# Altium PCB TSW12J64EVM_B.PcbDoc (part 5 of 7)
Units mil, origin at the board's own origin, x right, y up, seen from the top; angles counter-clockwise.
Board outline 8833 x 2680 mil, 10 copper layers (Top Layer L1, Gnd-Plane - L2, Signals - L3, Gnd-Plane - L4, Pwr Plane - L5, Signals - L6, Gnd-Plane - L7, Signals - L8, Gnd-Plane - L9, Bottom Layer - L10), stack 57.8 mil thick; 950 components, 533 nets, 2888 pads, 1732 vias.
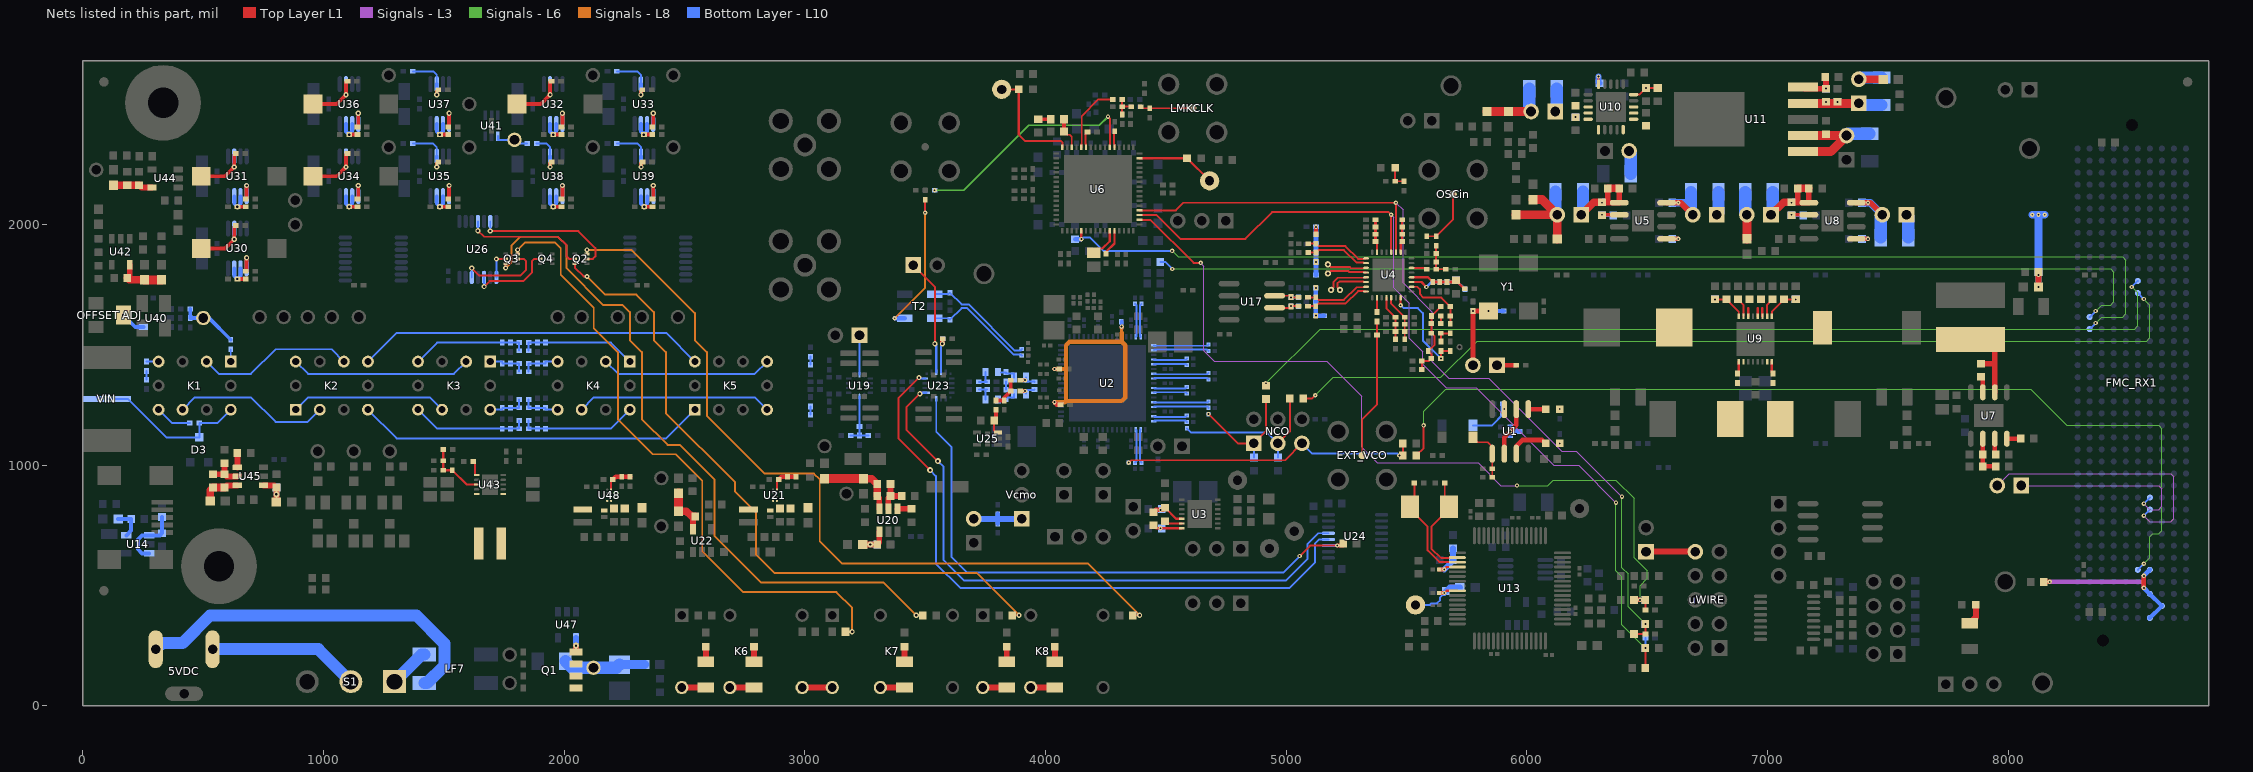
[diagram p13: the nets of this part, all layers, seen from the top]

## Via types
v1: diameter 18, hole 8, Top Layer L1 to Bottom Layer - L10, tented both sides, 1096 vias
v2: diameter 21.46, hole 10, Top Layer L1 to Bottom Layer - L10, tented both sides, 266 vias
v3: diameter 25, hole 10, Top Layer L1 to Bottom Layer - L10, tented both sides, 154 vias
v4: diameter 19.68, hole 7.87, Top Layer L1 to Bottom Layer - L10, 103 vias
v5: diameter 18, hole 8, Top Layer L1 to Bottom Layer - L10, tented bottom, 42 vias
v6: diameter 18, hole 8, Top Layer L1 to Bottom Layer - L10, tented top, 24 vias
v7: diameter 18, hole 8.01, Top Layer L1 to Bottom Layer - L10, tented both sides, 16 vias
v8: diameter 18, hole 8.01, Top Layer L1 to Bottom Layer - L10, tented bottom, 16 vias
v9: diameter 25.98, hole 12.99, Top Layer L1 to Bottom Layer - L10, tented top, 8 vias
v10: diameter 19.68, hole 7.87, Top Layer L1 to Bottom Layer - L10, tented top, 5 vias
v11: diameter 126, hole 106, Top Layer L1 to Bottom Layer - L10, tented top, 2 vias

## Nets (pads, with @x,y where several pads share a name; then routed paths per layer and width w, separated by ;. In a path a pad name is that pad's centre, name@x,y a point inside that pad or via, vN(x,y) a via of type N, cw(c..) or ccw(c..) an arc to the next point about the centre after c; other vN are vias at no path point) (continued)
LMH_SCSB: R187.1 U23.15 U24.11 | length 2428.3
  Top Layer L1 w8: v1(5056.02,622.21) 5099.42,665.61 v1(5212.13,665.61)
  Top Layer L1 w18: v1(5212.13,665.61) 5236.88,665.61 R187.1@5236.88,673.35
  Bottom Layer - L10 w8: U23.15@3546.04,1275.04 3546.04,1138.33 3609,1075.37 3609,619 3675,553 4986.8,553 v1(5056.02,622.21)
  Bottom Layer - L10 w13: U24.11@5175.57,665.61 v1(5212.13,665.61)
LMH_SDI: U23.1 U24.13 | length 2558.2
  Top Layer L1 w8: v2(3478.22,1296.66) 3422,1240.44 3422,1147.63 v3(3553,1016.63)
  Bottom Layer - L10 w8: v3(3553,1016.63) 3577,992.63 3577,605 3661,521 5000.06,521 5088.01,608.96 5088.01,671.18 5133.63,716.8 U24.13@5175.57,716.8
  Bottom Layer - L10 w9.84: v2(3478.22,1296.66) 3482.19,1300.63 U23.1@3504.7,1300.63
LMH_SDO: U23.4 U24.12 | length 2702.9
  Top Layer L1 w8: v2(3474.28,1363.65) 3390,1279.37 3390,1109.63 v3(3521,978.63)
  Bottom Layer - L10 w8: v3(3521,978.63) 3545,954.63 3545,591 3647,489 5013.31,489 5120.01,595.7 5120.01,674.9 5136.32,691.2 U24.12@5175.57,691.2
  Bottom Layer - L10 w9.84: v2(3474.28,1363.65) 3478.25,1359.68 U23.4@3500.76,1359.68
LMK04828_CSB: R68.1 R69.1 R98.1 R104.2 U6.18 | length 3453.2
  Top Layer L1 w8: U6.18@4390.79,2019.05 4435.95,2019.05 4615,1840 v1(4645,1840) ; R104.2@6492.44,398 R98.1@6492.44,440
  Top Layer L1 w18: R68.1@6445,440 R98.1@6492.44,440
  Signals - L3 w4: v1(4645,1840) 4658,1827 4658,1474 4701,1431 5169,1431 5313,1287 5313,1075 5378,1010 5797,1010 5892,915 v1(5959,915)
  Signals - L6 w4: v1(5959,915) 6087,915 6110,938 6370,938 6445,863 6445,616 6501,560 6501,529 6470.56,498.56 v1(6470.56,440)
  Bottom Layer - L10 w8: v1(6470.56,440) R69.1@6492.44,440
LMK04828_RESET: FMC_RX1.J16 R122.2 U6.5 | length 4841.4
  Top Layer L1 w9: v1(4148.66,1938.69) U6.5@4148.66,1973.77
  Signals - L6 w4: v1(4526,1890) 4551,1865 8475,1865 8488,1852 8488,1628 8475,1615 8388,1615 v5(8363,1590)
  Bottom Layer - L10 w8: v1(4148.66,1938.69) 4154.98,1945 4185,1945 4240,1890 v1(4526,1890) ; FMC_RX1.J16@8338,1565 v5(8363,1590)
  Bottom Layer - L10 w18: R122.2@4122.93,1938.69 v1(4148.66,1938.69)
LMK04828_SYNC: FMC_RX1.J15 R142.1 | length 4227.5
  Signals - L6 w4: v1(4526.55,1815) 8425,1815 8438,1802 8438,1678 8425,1665 8388,1665 v5(8363,1640)
  Bottom Layer - L10 w8: R142.1@4477.56,1843 4498.55,1843 v1(4526.55,1815) ; FMC_RX1.J15@8338,1615 v5(8363,1640)
LMK_TRF_CLK: R102.1 R115.1 R121.1 R129.2 U4.4 U6.19 | length 3794
  Top Layer L1 w8: U6.19@4390.79,2038.73 4461.27,2038.73 4560,1940 4830,1940 4941,2051 5425.08,2051 v1(5436.08,2040) U4.4@5436.08,1884.49 ; R102.1@6485.63,240 v1(6492.44,240) R115.1@6492.44,157.56
  Signals - L3 w4: v1(5436.08,2040) 5445.92,2030.16 5445.92,1737.08 5511,1672 5511,1527 5568,1470 5568,1419 5665,1322 5789,1322 6112.5,998.5 6215.5,998.5 v1(6370,844)
  Signals - L6 w4: v1(6370,844) 6370,560.44 6395,535.44 6395,337.44 v1(6492.44,240)
  Bottom Layer - L10 w8: v1(6492.44,240) R129.2@6492.44,282
LMK_TRF_DATA: R101.1 R114.1 R120.1 R128.2 U4.3 U6.20 | length 3686
  Top Layer L1 w8: U6.20@4390.79,2058.42 4541.42,2058.42 4573,2090 v1(5455.76,2090) U4.3@5455.76,1884.49 ; R114.1@6445,298 R128.2@6492.44,298 v1(6492.44,340)
  Signals - L3 w4: v1(5455.76,2090) 5485.29,2060.47 5485.29,1756.54 5607,1634.83 5607,1429 5675,1361 5841,1361 6144,1058 6206,1058 v1(6395,869)
  Signals - L6 w4: v1(6395,869) 6395,573 6420,548 6420,412.44 v1(6492.44,340)
LO1_N: C83.1 R34.2 U4.10 | length 266.8
  Top Layer L1 w8: C83.1@5091.73,1883.18 R34.2@5124.05,1883.18 5134.36,1893.5 5239.68,1893.5 5292.12,1841.05 5321.86,1841.05 5323.7,1839.21 U4.10@5331.75,1839.21
LO1_P: C75.1 R27.2 U4.9 | length 266.8
  Top Layer L1 w8: C75.1@5091.73,1919.81 R27.2@5124.05,1919.81 5134.36,1909.5 5246.3,1909.5 5298.75,1857.05 5321.86,1857.05 5323.7,1858.9 U4.9@5331.75,1858.9
LO2_N: LO2_N.1 U4.11 | length 166.2
  Top Layer L1 w8: LO2_N.1@5173.05,1833.99 5184.04,1823 5263.8,1823 5269.12,1817.68 5321.86,1817.68 5323.7,1819.53 U4.11@5331.75,1819.53
LO2_P: LO2_P.1 U4.12 | length 166.2
  Top Layer L1 w8: LO2_P.1@5173.05,1796.01 5184.04,1807 5257.18,1807 5262.49,1801.68 5321.86,1801.68 5323.7,1799.84 U4.12@5331.75,1799.84
LO3_N: LO3_N.1 U4.14 | length 153.6
  Top Layer L1 w8: LO3_N.1@5223.32,1728 5213,1738.31 5213,1754.63 5220.69,1762.31 5321.86,1762.31 5323.7,1760.47 U4.14@5331.75,1760.47
LO3_P: LO3_P.1 U4.13 | length 180.1
  Top Layer L1 w8: LO3_P.1@5186.69,1728 5197,1738.32 5197,1761.26 5214.06,1778.32 5321.86,1778.32 5323.7,1780.16 U4.13@5331.75,1780.16
LO4_N: C84.1 R35.2 U4.15 | length 267.8
  Top Layer L1 w8: C84.1@5090.73,1696.81 R35.2@5123.05,1696.81 5133.36,1686.5 5239.68,1686.5 5292.12,1738.95 5321.86,1738.95 5323.7,1740.79 U4.15@5331.75,1740.79
LO4_P: C76.1 R28.2 U4.16 | length 267.8
  Top Layer L1 w8: C76.1@5090.73,1660.18 R28.2@5123.05,1660.18 5133.36,1670.5 5246.3,1670.5 5298.75,1722.94 5321.86,1722.94 5323.7,1721.1 U4.16@5331.75,1721.1
NCO-0: NCO.1 R6.2 R7.1 R136.1 | length 502.4
  Top Layer L1 w8: v1(4677.2,1211.93) 4799.13,1090 NCO.1@4865.5,1090 4915.5,1140 R136.1@4915.5,1274.44
  Bottom Layer - L10 w8: R6.2@4865.5,1031.56 NCO.1@4865.5,1090
NCO-1: NCO.3 R5.2 R8.1 R137.1 | length 669.5
  Top Layer L1 w8: NCO.3@4965.5,1090 5015.5,1140 R137.1@5015.5,1276
  Bottom Layer - L10 w8: R8.1@4587.2,1152.88 4605.27,1134.81 4920.69,1134.81 NCO.3@4965.5,1090 R5.2@4965.5,1031.56
NCO-2: NCO.5 R4.2 R9.1 R138.1 | length 1227.9
  Top Layer L1 w8: v1(4345.86,1010.18) 4355.67,1020 4995.5,1020 NCO.5@5065.5,1090 ; R138.1@5484.94,1040 R4.2@5484.94,1090
  Bottom Layer - L10 w8: NCO.5@5065.5,1090 5106.5,1049 5461,1049 v1(5470,1040)
NCO_0: FMC_RX1.E12 R136.2 | length 3928.8
  Signals - L6 w4: v1(4915.5,1340) 5140.5,1565 8525,1565 8538,1578 8538,1715 v5(8513,1740)
  Bottom Layer - L10 w8: v5(8513,1740) FMC_RX1.E12@8538,1765
NCO_1: FMC_RX1.E13 R137.2 | length 3829.5
  Top Layer L1 w8: R137.2@5070.62,1276 5106.62,1276 v1(5120.62,1290)
  Signals - L6 w4: v1(5120.62,1290) 5195.62,1365 5643,1365 5793,1515 8575,1515 8588,1528 8588,1665 v5(8563,1690)
  Bottom Layer - L10 w8: FMC_RX1.E13@8538,1715 v5(8563,1690)
NCO_2: FMC_RX1.E36 R138.2 | length 4010.9
  Top Layer L1 w8: R138.2@5540.06,1040 5571,1070.94 v1(5571,1165)
  Signals - L6 w4: v1(5571,1165) 5571,1223 5663,1315 8093,1315 8243,1165 8625,1165 8638,1152 8638,728 8625,715 8601,715 8588,702 8588,615 v5(8563,590)
  Bottom Layer - L10 w8: FMC_RX1.E36@8538,565 v5(8563,590)
"Net1:1 Atten_1": "1:1 Atten.1" R253.2 | length 63.2
  Top Layer L1 w24: R253.2@3414,182.3 3414,245.47
Net1:1_2: 1:1.2 R235.1 U32.2 | length 256.4
  Top Layer L1 w15.75: 1:1.2@1804.52,2500 1903.36,2500 v2(1941.84,2538.48) 1941.84,2589.09 R235.1@1947.74,2595
  Bottom Layer - L10 w15.75: v2(1941.84,2538.48) U32.2@1941.84,2582.68
Net1V2ADC_INT_2: 1V2ADC_INT.2 C172.1 R83.2 U10.5 U10.6 U10.7 U10.8 | length 97.4
  Bottom Layer - L10 w51: 1V2ADC_INT.2@6424.26,2305 6431.35,2297.91 R83.2@6431.35,2210.56
Net1V2ADC_LDO_1: 1V2ADC_LDO.1 C185.1 C195.1 R84.1 R85.2 U10.1 U10.18 U10.19 U10.20 | length 97.4
  Bottom Layer - L10 w51: 1V2ADC_LDO.1@6117.27,2469 6124.35,2476.09 R84.1@6124.35,2563.44
  other v1: 6202.68,2445.56
Net1V2ADC_LDO_2: 1V2ADC_LDO.2 L15.1 L16.1 R84.2 | length 279.6
  Top Layer L1 w37: L15.1@5835,2469 L16.1@5923,2469 1V2ADC_LDO.2@6017.27,2469
  Bottom Layer - L10 w51: R84.2@6010.18,2563.44 6010.18,2476.09 1V2ADC_LDO.2@6017.27,2469
Net1V9ADC_1: 1V9ADC.1 C192.1 C198.1 C204.1 R92.1 R93.2 U11.4 | length 377.2
  Top Layer L1 w37: U11.4@7147.22,2502.93 1V9ADC.1@7379,2502.93
  Bottom Layer - L10 w24: v1(7243,2508.83) v1(7291,2508.83)
  Bottom Layer - L10 w51: 1V9ADC.1@7379,2502.93 7386.09,2495.84 R92.1@7473.44,2495.84
Net1V9ADC_2: 1V9ADC.2 L18.1 R92.2 | length 197.9
  Top Layer L1 w31.5: 1V9ADC.2@7379,2602.93 L18.1@7479.5,2602.93
  Bottom Layer - L10 w51: 1V9ADC.2@7379,2602.93 7386.09,2610.02 R92.2@7473.44,2610.02
Net1V9INT_2: 1V9INT.2 C196.1 R95.2 U11.1 U11.2 | length 487
  Top Layer L1 w37: U11.1@7147.22,2302.14 7262.07,2302.14 1V9INT.2@7328,2369.07 U11.2@7147.22,2369.07
  Bottom Layer - L10 w51: 1V9INT.2@7328,2369.07 7335.09,2376.16 R95.2@7422.44,2376.16
"Net2:1 Atten_1": "2:1 Atten.1" R252.1 | length 63.2
  Top Layer L1 w24: R252.1@2789,182.3 2789,245.47
Net2:1_2: 2:1.2 R237.1 U34.2 | length 256.4
  Top Layer L1 w15.75: 2:1.2@956.52,2200 1055.36,2200 v2(1093.84,2238.48) 1093.84,2289.09 R237.1@1099.74,2295
  Bottom Layer - L10 w15.75: v2(1093.84,2238.48) U34.2@1093.84,2282.68
Net3P3USB_1: 3P3USB.1 C139.1 C140.1 L24.2 U13.9 | length 301.4
  Top Layer L1 w10: v1(5656.5,468.31) 5666.34,478.16 U13.9@5710.97,478.16
  Top Layer L1 w16.5: C140.1@5635.44,468.32 v1(5656.5,468.31)
  Bottom Layer - L10 w8: 3P3USB.1@5537,419 5597,419 5603,425 5626,425 5639,438 5639,450.81 v1(5656.5,468.31)
  Bottom Layer - L10 w24: v1(5656.5,468.31) 5679.18,491 L24.2@5721.5,491
"Net5:1 Atten_1": "5:1 Atten.1" R251.2 | length 63.2
  Top Layer L1 w24: R251.2@2589,182.3 2589,245.47
Net5:1_2: 5:1.2 R238.1 U36.2 | length 256.4
  Top Layer L1 w15.75: 5:1.2@956.52,2500 1055.36,2500 v2(1093.84,2538.48) 1093.84,2589.09 R238.1@1099.74,2595
  Bottom Layer - L10 w15.75: v2(1093.84,2538.48) U36.2@1093.84,2582.68
Net5VDC_1: 5VDC.1 S1.2 | length 630.5
  Bottom Layer - L10 w50: 5VDC.1@539.37,235 979.2,235 S1.2@1114,100.2
Net5VDC_2: 5VDC.2 LF7.1 | length 1511.5
  Bottom Layer - L10 w50: 5VDC.2@303.15,235 329.15,261 415,261 529.51,375.51 1385.79,375.51 1503,258.31 1503,166.89 1430.6,94.49 LF7.1@1419.55,94.49
Net12V_1: 12V.1 R94.1 | length 88.2
  Top Layer L1 w25: R94.1@7840,342.15 7865,367.15 12V.1@7865,420
"Net5401 PD_1": "5401 PD.1" U19.9 | length 163.6
  Bottom Layer - L10 w8: U19.9@3227.22,1375.43 3227.22,1539
"Net6401 PD_1": "6401 PD.1" U23.6 | length 485.5
  Top Layer L1 w8: 3450.06,1831 3540.23,1740.83 v2(3540.23,1504.43)
  Bottom Layer - L10 w9.84: v2(3540.23,1504.43) 3546.04,1498.61 U23.6@3546.04,1385.28
Net+5_1: +5.1 C193.1 F1.1 L17.1 Q1.1 Q1.2 Q1.3 | length 346.3
  Bottom Layer - L10 w37: C193.1@2230,171.39 L17.1@2334.5,171.39
  Bottom Layer - L10 w50: F1.1@2005.09,185.3 2032.39,158 +5.1@2122,158 2216.61,158 C193.1@2230,171.39
"NetAC COUPLED_1": "AC COUPLED.1" R254.2 | length 63.2
  Top Layer L1 w24: R254.2@3839,182.3 3839,245.47
NetAC_2: AC.2 R236.1 U31.2 | length 256.4
  Top Layer L1 w15.75: AC.2@492.52,2200 591.36,2200 v2(629.84,2238.48) 629.84,2289.09 R236.1@635.74,2295
  Bottom Layer - L10 w15.75: v2(629.84,2238.48) U31.2@629.84,2282.68
NetC1_2: C1.2 R184.2 R185.1 R190.2 | length 129.3
  Top Layer L1 w16: R190.2@3794.43,1268.69 C1.2@3828.43,1268.69 3828.43,1280.56 R184.2@3855.42,1307.55 R185.1@3855.42,1352.76
NetC2_1: C2.1 D2.1 R3.2 U1.3 | length 187.3
  Bottom Layer - L10 w8: D2.1@5775.95,1165 5855.02,1165 C2.1@5900.69,1210.67
  Bottom Layer - L10 w19.5: C2.1@5900.69,1210.67 R3.2@5900.69,1254.36
  other v1: 5906,1232.52
NetC7_2: C7.2 U2.33 | length 139.9
  Bottom Layer - L10 w8: U2.33@4395.18,1532.91 4393.34,1534.76 4393.34,1664.32 C7.2@4398.84,1669.81
NetC8_1: C8.1 D4.1 R11.2 U1.5 | length 222.2
  Top Layer L1 w8: D4.1@5775.95,1115 5795.95,1095 5837,1095 5856,1076 U1.5@5856,1047.48 C8.1@5856,985 R11.2@5856,950
NetC9_2: C9.2 U2.32 | length 139.9
  Bottom Layer - L10 w8: C9.2@4371.84,1669.81 4377.34,1664.31 4377.34,1534.76 U2.32@4375.5,1532.91
NetC10_2: C10.2 U2.36 | length 229.9
  Bottom Layer - L10 w8: U2.36@4450.3,1477.8 4452.14,1479.64 4671.7,1479.64 C10.2@4677.2,1474.14
NetC11_1: C11.1 R1.1 R12.2 U1.2 U1.6 | length 281.1
  Top Layer L1 w19.5: U1.6@5906,1047.48 5906,1115 v1(5931,1140) 5956,1165 U1.2@5956,1232.52
  Bottom Layer - L10 w19.5: R12.2@5931,1122 C11.1@5931,1158 ; v1(5931,1140) R1.1@5970.31,1140
NetC12_2: C12.2 U2.35 | length 229.9
  Bottom Layer - L10 w8: U2.35@4450.3,1497.48 4452.14,1495.64 4671.7,1495.64 C12.2@4677.2,1501.14
NetC13_2: C13.2 U2.39 | length 139.9
  Bottom Layer - L10 w8: U2.39@4450.3,1418.74 4452.14,1420.58 4581.7,1420.58 C13.2@4587.2,1415.08
NetC14_2: C14.2 U2.38 | length 139.9
  Bottom Layer - L10 w8: U2.38@4450.3,1438.43 4452.14,1436.58 4581.7,1436.58 C14.2@4587.2,1442.08
NetC15_2: C15.2 U2.42 | length 229.9
  Bottom Layer - L10 w8: U2.42@4450.3,1359.68 4452.14,1361.53 4671.7,1361.53 C15.2@4677.2,1356.03
NetC16_2: C16.2 C18.2 C19.2 U2.5 U2.12 U2.29 | length 1287.4
  Top Layer L1 w18: v1(4037.26,1261.26) 4047.31,1251.21 C18.2@4062.57,1251.2 ; v1(4037.26,1399.05) C19.2@4057.52,1399.05
  Signals - L8 w13: 4316.44,1549.33 v1@4316.44,1570.92
  Signals - L8 w18: v1(4037.26,1261.26) 4080.22,1261.26 4085.14,1266.18 ; v1(4037.26,1399.05) 4085.14,1399.05 ; 4084.79,1497.48 4099.56,1512.24 4316.79,1512.24 ; 4085.14,1497.83 4085.14,1266.18 ; 4316.44,1549.33 4316.44,1512.59 4331.2,1497.83 4331.2,1280.6 4316.79,1266.18 4085.14,1266.18 ; v1@4316.44,1570.92 v1(4316.44,1575.13)
  Bottom Layer - L10 w9: v1(4037.26,1261.26) U2.5@4064.47,1261.26 ; v1(4037.26,1399.05) U2.12@4064.47,1399.06 ; U2.29@4316.44,1532.91 v1(4316.44,1575.13)
  Bottom Layer - L10 w16: v1(4316.44,1575.13) C16.2@4316.44,1595.94
NetC17_2: C17.2 U2.41 | length 229.9
  Bottom Layer - L10 w8: U2.41@4450.3,1379.37 4452.14,1377.53 4671.7,1377.53 C17.2@4677.2,1383.03
NetC20_2: C20.2 U2.45 | length 139.9
  Bottom Layer - L10 w8: U2.45@4450.3,1300.63 4452.14,1302.47 4581.7,1302.47 C20.2@4587.2,1296.97
NetC21_2: C21.2 U2.44 | length 139.9
  Bottom Layer - L10 w8: U2.44@4450.3,1320.31 4452.14,1318.47 4581.7,1318.47 C21.2@4587.2,1323.97
NetC22_2: C22.2 R7.2 U2.48 | length 229.9
  Bottom Layer - L10 w8: U2.48@4450.3,1241.57 4452.14,1243.42 4671.7,1243.42 R7.2@4677.2,1237.92
NetC23_2: C23.2 U2.47 | length 229.9
  Bottom Layer - L10 w8: U2.47@4450.3,1261.26 4452.14,1259.42 4671.7,1259.42 C23.2@4677.2,1264.92
NetC26_2: C26.2 R8.2 U2.51 | length 139.9
  Bottom Layer - L10 w8: U2.51@4450.3,1182.52 4452.14,1184.36 4581.7,1184.36 R8.2@4587.2,1178.86
NetC28_2: C28.2 U2.50 | length 139.9
  Bottom Layer - L10 w8: U2.50@4450.3,1202.2 4452.14,1200.36 4581.7,1200.36 C28.2@4587.2,1205.86
NetC29_2: C29.2 R9.2 U2.54 | length 139.9
  Bottom Layer - L10 w8: R9.2@4371.84,1010.18 4377.34,1015.68 4377.34,1145.24 U2.54@4375.5,1147.09
NetC30_2: C30.2 C229.1 T2.4 | length 465.7
  Bottom Layer - L10 w8: T2.4@3540.25,1609.95 3596.67,1609.95 C229.1@3602.85,1603.77 3651.03,1651.95 3674.41,1651.95 3866.41,1459.95 3896.09,1459.95 C30.2@3901.59,1454.45
NetC31_2: C31.2 U2.53 | length 139.9
  Bottom Layer - L10 w8: U2.53@4395.18,1147.09 4393.34,1145.24 4393.34,1015.69 C31.2@4398.84,1010.19
NetC34_1: C34.1 U3.6 | length 72.4
  Top Layer L1 w10: C34.1@4497.28,767.44 4507.33,757.39 U3.6@4565.47,757.39
NetC34_2: C34.2 C38.2 R100.2 U3.5 | length 143.5
  Top Layer L1 w10: C34.2@4497.28,822.56 4542.76,777.07 U3.5@4565.47,777.07
  Top Layer L1 w18: C38.2@4448.28,804.56 4457.72,814 4488.72,814 C34.2@4497.28,822.56
  other v1: 4477.78,814
NetC36_2: C36.2 C228.1 T2.6 | length 465.7
  Bottom Layer - L10 w8: T2.6@3540.25,1709.95 3596.67,1709.95 C228.1@3602.85,1716.14 3651.03,1667.95 3681.03,1667.95 3873.03,1475.95 3896.09,1475.95 C36.2@3901.59,1481.45
NetC38_1: C38.1 R99.2 U3.7 | length 122.1
  Top Layer L1 w10: C38.1@4448.28,749.44 4460.02,737.7 U3.7@4565.47,737.7
  other v1: 4477.78,737.7
NetC73_2: C73.2 C74.2 J2.2 R133.2 Y1.4 | length 352.6
  Top Layer L1 w19.68: J2.2@5776,1415 v1(5776,1640) v1(5840.56,1640)
  Bottom Layer - L10 w18: v1(5840.56,1640) R133.2@5903.55,1640
NetC76_2: C76.2 R33.2 R162.2 R163.1 U17.2 | length 134.6
  Top Layer L1 w8: U17.2@4951.82,1653.5 5013.36,1653.5 v1(5020.05,1660.18) C76.2@5051.36,1660.18 C76.2@5052.36,1660.18
  Bottom Layer - L10 w8: v1(5020.05,1660.18) R163.1@5051.36,1660.18
NetC77_1: C77.1 C78.1 C81.1 L1.2 R27.1 R34.1 | length 230.8
  Top Layer L1 w18: R27.1@5124.05,1959.18 v1(5124.05,1990)
  Bottom Layer - L10 w19.68: L1.2@5124.05,1790 v1(5124.05,1843.81) v1(5124.05,1990)
NetC79_1: C79.1 C80.1 C82.1 L34.2 R28.1 R35.1 | length 149.6
  Bottom Layer - L10 w19.68: v1(5123.05,1736.18) v1(5123.05,1620.81) L34.2@5157.32,1620.82
NetC84_2: C84.2 R37.2 R162.1 R164.1 U17.3 | length 126.1
  Top Layer L1 w8: U17.3@4951.82,1703.5 R162.1@5013.36,1703.5 ; R162.1@5019.36,1697.5 v1(5020.05,1696.81) C84.2@5051.36,1696.81 C84.2@5052.36,1696.81
  Bottom Layer - L10 w8: v1(5020.05,1696.81) R164.1@5051.36,1696.82
NetC85_2: C85.2 U6.43 | length 67.8
  Top Layer L1 w8: U6.43@4168.35,2320.23 4168.35,2332.23 4166.5,2334.07 4166.5,2376.19 C85.2@4174.31,2384
NetC86_1: C86.1 C123.2 R48.1 R50.1 | length 99.6
  Top Layer L1 w8: C123.2@4318.67,2456.69 R50.1@4318.67,2489 ; C86.1@4318.67,2519 R50.1@4318.67,2489 ; R48.1@4355.98,2489 R50.1@4318.67,2489
NetC86_2: C86.2 U6.44 | length 287.6
  Top Layer L1 w8: U6.44@4148.66,2320.23 4148.66,2332.23 4150.5,2334.07 4150.5,2449.5 4220,2519 C86.2@4279.3,2519
NetC87_1: C87.1 U6.38 | length 978.6
  Top Layer L1 w8: v1(4259.61,2447.5) 4268.61,2438.5 4268.61,2334.07 4266.77,2332.23 U6.38@4266.77,2320.23
  Signals - L6 w8: v1(3539.43,2141.68) 3659.69,2141.68 3930,2412 4224.12,2412 v1(4259.61,2447.5)
NetC88_1: C88.1 U6.37 | length 69.3
  Top Layer L1 w8: U6.37@4286.46,2320.23 4286.46,2332.23 4284.61,2334.07 4284.61,2383.93 C88.1@4288,2387.32
NetC89_2: C89.2 T2.3 | length 586.2
  Top Layer L1 w8: v1(3500.06,2048.5) C89.2@3500.06,2102.31
  Signals - L8 w8: v1(3373.57,1609.95) 3500.06,1736.43 v1(3500.06,2048.5)
  Bottom Layer - L10 w18: v1(3373.57,1609.95) T2.3@3415.06,1609.95
NetC99_2: C99.2 R190.1 U25.3 | length 101.3
  Top Layer L1 w8: C99.2@3786.68,1186 3786.68,1143.44 3794.53,1135.59 U25.3@3803.41,1135.59
  Top Layer L1 w16: C99.2@3794.43,1190.58 R190.1@3794.43,1229.32
NetC117_1: C117.1 C126.1 C166.1 LMK_LDO.1 R40.1 R41.2 U5.5 | length 443.2
  Top Layer L1 w23.5: C117.1@6312,2092.56 6314.56,2090 U5.5@6383.57,2090 C126.1@6383.57,2150 ; 6336.56,2090 C166.1@6336.56,2150
  Top Layer L1 w31.5: LMK_LDO.1@6226,2040 6278.56,2092.56 C117.1@6309.44,2092.56 ; C166.1@6336.56,2150 C126.1@6383.57,2150
  Bottom Layer - L10 w51: LMK_LDO.1@6226,2040 6233.09,2047.09 R40.1@6233.09,2135.44
  other v1: 6312,2090
NetC117_2: C117.2 R41.1 R49.2 U5.6 | length 120.1
  Top Layer L1 w15: C117.2@6312,2037.44 6314.56,2040 U5.6@6383.57,2040
  Bottom Layer - L10 w15: R41.1@6312,2037.44 R49.2@6359.44,2037.44
  other v1: 6312,2040
NetC122_1: C122.1 U6.11 | length 129.3
  Top Layer L1 w9: C122.1@4200.9,1882.27 4218.37,1899.74 4236.3,1899.74 4266.77,1930.21 U6.11@4266.77,1973.77
NetC124_1: C124.1 U6.12 | length 110.9
  Top Layer L1 w9: C124.1@4251.3,1877.43 4251.3,1885.74 4286.46,1920.9 U6.12@4286.46,1973.77
NetC127_1: C127.1 LMK_INT.2 R42.2 U5.4 | length 304.5
  Top Layer L1 w23.5: U5.4@6580.43,2090 v1(6628.79,2090) 6639,2090 LMK_INT.2@6689,2040
  Bottom Layer - L10 w31.5: C127.1@6604.05,2090 v1(6628.79,2090) 6681.91,2090
  Bottom Layer - L10 w51: R42.2@6681.91,2134.44 6681.91,2047.09 LMK_INT.2@6689,2040
NetC128_1: C128.1 U5.1 | length 73.1
  Top Layer L1 w18: U5.1@6580.43,1940 v1(6628.8,1940)
  Bottom Layer - L10 w18: C128.1@6604.05,1940 v1(6628.8,1940)
NetC135_1: C135.1 U13.2 Y2.1 | length 435
  Top Layer L1 w8: C135.1@5658.65,926 5658.65,844.53 Y2.1@5676.18,827 5676.18,816.71 5603.47,744 5603.47,652.63 5641.99,614.11 5676.63,614.11 5678.47,615.95 U13.2@5710.97,615.95
NetC137_1: C137.1 U13.3 Y2.2 | length 461.5
  Top Layer L1 w8: C137.1@5532.29,926 5532.29,844.53 Y2.2@5514.76,827 5514.76,816.71 5587.47,744 5587.47,646 5635.36,598.11 5676.63,598.11 5678.47,596.27 U13.3@5710.97,596.27
NetC141_1: C141.1 C142.1 L25.2 U13.4 | length 182.2
  Top Layer L1 w10: v1(5656.5,566.74) 5666.34,576.58 U13.4@5710.97,576.58
  Top Layer L1 w16.5: C142.1@5635.44,566.74 v1(5656.5,566.74)
  Bottom Layer - L10 w24: v1(5656.5,566.74) 5692.56,602.8 C141.1@5692.56,606 L25.2@5692.56,654.44
NetC148_1: C148.1 L8.1 U7.6 | length 378.7
  Top Layer L1 w23.62: L8.1@7843,1522.46 7944,1522.46 U7.6@7944,1302.46 ; C148.1@7886.27,1421.56 7944,1421.56
NetC148_2: C148.2 U7.7 | length 67.2
  Top Layer L1 w18: C148.2@7886.27,1366.44 7894,1358.71 U7.7@7894,1302.46
NetC149_1: C149.1 C150.1 C151.1 LMX_LDO.1 R73.1 R74.2 U8.5 | length 442.2
  Top Layer L1 w23.5: C149.1@7100,2092.56 7102.56,2090 U8.5@7171.57,2090 C151.1@7171.57,2150 ; 7124.56,2090 C150.1@7124.56,2150
  Top Layer L1 w31.5: LMX_LDO.1@7014,2040 7066.56,2092.56 C149.1@7097.44,2092.56 ; C150.1@7124.56,2150 C151.1@7171.57,2150
  Bottom Layer - L10 w51: LMX_LDO.1@7014,2040 7021.09,2047.09 R73.1@7021.09,2134.44
  other v1: 7100,2090
NetC149_2: C149.2 R74.1 R77.2 U8.6 | length 120.1
  Top Layer L1 w15: C149.2@7100,2037.44 7102.56,2040 U8.6@7171.57,2040
  Bottom Layer - L10 w15: R74.1@7100,2037.44 R77.2@7147.44,2037.44
  other v1: 7100,2040
NetC154_1: C154.1 R72.2 R76.2 U7.2 | length 168
  Top Layer L1 w18: U7.2@7894,1109.54 R72.2@7894,995 R76.2@7947.44,995
NetC155_1: C155.1 U7.3 | length 65.5
  Top Layer L1 w18: C155.1@7944,1044 U7.3@7944,1109.54
NetC158_1: C158.1 C159.1 L7.2 LMK_INT.1 LMX_INT.1 R42.1 R75.1 | length 610.3
  Top Layer L1 w24: v1(8125.5,1739.21) C159.1@8125.5,1802
  Bottom Layer - L10 w24: v1(8125.5,1739.21) C158.1@8125.5,1802
  Bottom Layer - L10 w31.5: v1(8099.5,2040) v1(8151.5,2040) ; C158.1@8125.5,1802 v1(8125.5,2040)
  Bottom Layer - L10 w51: LMK_INT.1@6789,2040 6796.09,2047.09 R42.1@6796.09,2134.44 ; LMX_INT.1@7577,2040 7584.09,2032.91 R75.1@7584.09,1945.56
  other v1: 8125.5,1790
NetC160_1: C160.1 LMX_INT.2 R75.2 U8.4 | length 332.3
  Top Layer L1 w23.5: U8.4@7368.43,2090 v1(7416.79,2090) 7427,2090 LMX_INT.2@7477,2040
  Bottom Layer - L10 w31.5: C160.1@7392.05,2090 v1(7416.79,2090) 7427,2090 LMX_INT.2@7477,2040
  Bottom Layer - L10 w51: R75.2@7469.91,1945.56 7469.91,2032.91 LMX_INT.2@7477,2040
NetC161_1: C161.1 U8.1 | length 73.1
  Top Layer L1 w18: U8.1@7368.43,1940 v1(7416.8,1940)
  Bottom Layer - L10 w18: C161.1@7392.05,1940 v1(7416.8,1940)
NetC162_1: C162.1 U7.4 | length 57.4
  Top Layer L1 w18: U7.4@7994,1109.54 C162.1@8051.44,1109.54
NetC168_1: C168.1 R78.2 U9.3 U9.4 U9.6 | length 100.5
  Top Layer L1 w10: U9.6@6919.47,1618.49 6919.47,1652 ; U9.4@6958.84,1618.49 6958.84,1652 ; U9.3@6978.53,1618.49 6978.53,1652
NetC169_1: C169.1 U9.16 | length 50.8
  Top Layer L1 w10: U9.16@7017.9,1429.51 7017.9,1385.53 C169.1@7022.74,1380.68
NetC169_2: C169.2 D5.1 L11.2 U9.15
NetC170_1: C170.1 D6.1 L12.1 U9.10
NetC170_2: C170.2 U9.9 | length 50.8
  Top Layer L1 w10: C170.2@6875.26,1380.69 6880.1,1385.53 U9.9@6880.1,1429.51
NetC174_1: C174.1 R81.2 R86.2 U9.1 | length 139.1
  Top Layer L1 w8: U9.1@7017.9,1618.49 7017.9,1637.34 R86.2@7069,1688.44 v1(7117,1688.44)
NetC175_2: C175.2 R82.1 R87.2 U9.8 | length 139.1
  Top Layer L1 w8: v1(6781,1688.44) R87.2@6829,1688.44 6880.1,1637.34 U9.8@6880.1,1618.49
NetC178_1: C178.1 U9.2 | length 79.4
  Top Layer L1 w8: U9.2@6998.21,1618.49 6998.21,1665.65 C178.1@7021,1688.44
NetC179_1: C179.1 U9.7 | length 79.4
  Top Layer L1 w8: C179.1@6877,1688.44 6899.79,1665.65 U9.7@6899.79,1618.49
NetC186_1: C186.1 R79.1 R90.2 U10.10 | length 111.9
  Top Layer L1 w8: U10.10@6443.16,2539.18 6467.3,2539.18 v1(6494.68,2566.56) R79.1@6543.68,2566.56
NetC187_1: C187.1 U10.15 | length 61.2
  Top Layer L1 w8: U10.15@6297.49,2582.49 v1(6297.49,2614.17)
  Bottom Layer - L10 w24: v1(6297.49,2614.17) 6297.49,2590.61 C187.1@6301.67,2586.43
NetC192_2: C192.2 R93.1 R96.2 U11.5 | length 147.7
  Top Layer L1 w24: U11.5@7147.22,2569.86 7153.13,2563.95 v1(7243,2563.95) 7243,2608.44 R96.2@7239.44,2612
NetC201_1: C201.1 R103.2 U14.1 U14.3 | length 271.6
  Bottom Layer - L10 w16.5: U14.3@275.94,633.46 246.64,633.46 229.76,650.33 229.76,691.39 246.64,708.26 U14.1@275.94,708.26 320.38,708.26 C201.1@329.24,717.12 R103.2@329.24,784.4
NetC211_1: C211.1 L26.1 U14.5 | length 130.2
  Bottom Layer - L10 w16.5: L26.1@146.73,775.86 C211.1@201.14,775.86 201.14,727.95 U14.5@181.46,708.26
NetC230_1: C230.1 C231.2 C232.1 C233.1 L27.2 U4.27 | length 256.3
  Top Layer L1 w9.45: U4.27@5520.72,1760.47 5561.69,1760.47 v1(5582.17,1740)
  Bottom Layer - L10 w11.02: v1(5582.17,1740) 5602.64,1760.47 C233.1@5608.33,1760.47 C232.1@5638.33,1760.47 C231.2@5668.33,1760.47 5698.46,1760.47 C230.1@5705.33,1767.35 L27.2@5742,1730.68
NetC234_1: C234.1 C235.2 C236.1 C237.1 L28.2 U4.28 | length 244
  Top Layer L1 w9.45: U4.28@5520.72,1780.16 5588.65,1780.16 C237.1@5608.33,1760.47
  Top Layer L1 w11.02: C237.1@5608.33,1760.47 C236.1@5638.33,1760.47 C235.2@5668.33,1760.47 5698.46,1760.47 C234.1@5705.33,1767.35 L28.2@5739.55,1733.13
NetC238_1: C238.1 C239.1 C240.1 L29.2 U4.21 | length 196.5
  Top Layer L1 w8: U4.21@5436.08,1695.51 5436.08,1671.16 C238.1@5492.55,1614.68 C239.1@5492.55,1584.68 C240.1@5492.55,1554.68 L29.2@5492.55,1522.37
NetC241_1: C241.1 C242.1 C243.1 L30.2 U4.20 | length 188.7
  Top Layer L1 w8: U4.20@5416.39,1695.51 5416.39,1652.21 C241.1@5453.92,1614.68 C242.1@5453.92,1584.68 C243.1@5453.92,1554.68 L30.2@5453.92,1522.37
NetC244_1: C244.1 C245.1 R91.1 U4.26 | length 278.6
  Top Layer L1 w8: U4.26@5520.72,1740.79 5545.08,1740.79 5555.14,1730.72 5555.14,1711.28 5570.33,1696.09 5644.57,1696.09 C245.1@5681.98,1658.68 C244.1@5681.98,1619.31 R91.1@5681.98,1586.68
NetC244_2: C244.2 R144.2 | length 31.3
  Top Layer L1 w8: R144.2@5642.61,1588 C244.2@5642.61,1619.31
NetC245_2: C245.2 C246.2 C247.2 R144.1 R145.2 R146.2 R147.1 R149.1 | length 332.4
  Top Layer L1 w8: R147.1@5563.68,1397.5 R146.2@5563.68,1432.5 5592.74,1432.5 C247.2@5603.24,1443 5603.24,1461.31 R149.1@5590.24,1474.31 5616.24,1500.31 5616.24,1534.31 C246.2@5603.24,1547.31 R144.1@5603.24,1588 R145.2@5603.24,1619.31 C245.2@5642.61,1658.68
NetC246_1: C246.1 R91.2 R148.1 | length 73
  Top Layer L1 w8: R148.1@5642.61,1513.68 C246.1@5642.61,1547.31 R91.2@5681.98,1547.31
NetC247_1: C247.1 R148.2 R150.1 U4.23 | length 426.8
  Top Layer L1 w8: v1@5475.45,1664.93 U4.23@5475.45,1695.51 ; v1(5642.61,1443) R148.2@5642.61,1474.31 R150.1@5681.98,1474.31
  Bottom Layer - L10 w8: v1@5475.45,1664.93 5488.38,1652 5547,1652 5568,1631 5568,1517.61 v1(5642.61,1443)
  other v1: 5475.45,1664.07
NetC248_1: C248.1 U4.18 | length 59.8
  Top Layer L1 w8: C248.1@5377.02,1635.68 U4.18@5377.02,1695.51
NetC248_2: C248.2 EXT_VCO.1 R153.2 | length 581.6
  Top Layer L1 w8: EXT_VCO.1@5316.02,1040 5316.02,1190.02 5377.02,1251.02 R153.2@5377.02,1540 C248.2@5377.02,1596.31
NetC249_1: C249.1 U4.30 | length 65.3
  Top Layer L1 w8: U4.30@5520.72,1819.53 5577.8,1819.53 C249.1@5583.65,1813.69
NetC249_2: C249.2 C251.2 R24.2 R25.2 R38.1 | length 137
  Top Layer L1 w8: R25.2@5623.02,1911.41 C249.2@5623.02,1813.69 R38.1@5662.31,1813.68
NetC250_2: C250.2 LD.1 R154.1 | length 92.3
  Top Layer L1 w8: LD.1@5452.69,2235.37 C250.2@5452.68,2179.37 R154.1@5489,2179.37
NetC252_1: C252.1 C253.1 C254.1 L32.2 U4.2 | length 137.2
  Top Layer L1 w8: C254.1@5481.75,1929.09 L32.2@5481.75,2019.09
  Top Layer L1 w9.45: U4.2@5475.45,1884.49 5475.45,1922.8 C254.1@5481.75,1929.09
NetC255_1: C255.1 C256.1 C257.1 L33.2 U4.7 | length 137.2
  Top Layer L1 w9.45: C257.1@5370.72,1929.09 5377.02,1922.8 U4.7@5377.02,1884.49
  Top Layer L1 w11.02: C257.1@5370.72,1929.09 C256.1@5370.72,1959.09 C255.1@5370.72,1989.09 L33.2@5370.72,2019.09
NetC272_2: C272.2 R178.2 R188.1 R189.2 U19.2 | length 235.6
  Bottom Layer - L10 w8: R189.2@3190.52,1122.68 R178.2@3227.22,1122.68 ; U19.2@3227.22,1284.88 C272.2@3227.22,1160 R178.2@3227.22,1122.68 ; R188.1@3263.93,1122.68 R178.2@3227.22,1122.68
NetC276_1: C276.1 C277.1 L35.2 U20.1 | length 146.1
  Top Layer L1 w24: L35.2@3240.31,670 v3(3272.49,670) C277.1@3300.74,670 3309.6,678.86 U20.1@3309.6,723.76
  Bottom Layer - L10 w24: v3(3272.49,670) C276.1@3300.74,670
NetC278_1: C278.1 U20.4 | length 59.6
  Top Layer L1 w24: U20.4@3384.4,818.24 C278.1@3444,818.24
NetC279_1: C279.1 L43.1 L45.1 R171.1 U20.6 | length 334.7
  Top Layer L1 w24: R171.1@3300.74,872 3309.6,863.14 U20.6@3309.6,818.24
  Top Layer L1 w31.5: L45.1@3244.01,943.97 3277.77,943.97 C279.1@3300.74,921 R171.1@3300.74,872
  Top Layer L1 w37.4: L43.1@3082.01,943.97 L45.1@3244.01,943.97
NetC279_2: C279.2 R171.2 R172.2 U20.5 | length 153
  Top Layer L1 w24: U20.5@3347,818.24 3347,863.14 R171.2@3355.86,872 ; C279.2@3355.86,921 R171.2@3355.86,872 ; R172.2@3402.44,872 R171.2@3355.86,872
NetC282_1: C282.1 C283.1 L36.2 U21.D2
NetC286_2: C286.2 R174.1 R175.2 U21.A2 | length 125.3
  Top Layer L1 w8: U21.A2@2883.86,898.65 2883.86,940.02 R175.2@2891.67,940.02
  Top Layer L1 w19: R175.2@2891.67,940.02 2903.36,951.71 R174.1@2927.99,951.71 C286.2@2962.99,951.71
NetC291_1: C291.1 L38.1 R211.2 | length 75.8
  Bottom Layer - L10 w8: R211.2@3723,1314.47 C291.1@3757.31,1314.47 ; L38.1@3750.92,1273.01 C291.1@3750.92,1314.47
NetC292_2: C292.2 L39.1 R212.2 | length 75.8
  Bottom Layer - L10 w8: R212.2@3723,1345.84 C292.2@3757.31,1345.84 ; C292.2@3750.92,1345.84 L39.1@3750.92,1387.3
NetC293_1: C293.1 L38.2 L55.1 | length 81.8
  Bottom Layer - L10 w8: L38.2@3803.08,1273.47 C293.1@3836,1273.47 ; C293.1@3836,1280.39 3868.8,1280.39 L55.1@3868.8,1296.47
NetC293_2: C293.2 C294.1 | length 34.6
  Bottom Layer - L10 w8: C293.2@3836,1312.84 C294.1@3836,1347.47
NetC294_2: C294.2 L39.2 L56.1 | length 70.9
  Bottom Layer - L10 w8: L39.2@3814,1384.84 C294.2@3836,1384.84 ; C294.2@3836,1379.92 3868.8,1379.92 L56.1@3868.8,1363.84
NetC295_1: C295.1 R168.2 | length 33.6
  Bottom Layer - L10 w8: R168.2@3024.02,1209.69 C295.1@3024.02,1243.32
NetC296_1: C296.1 R204.2 | length 33.6
  Bottom Layer - L10 w8: C296.1@3024.02,1417 R204.2@3024.02,1450.63
NetC309_2: C309.2 R181.2 U23.7 | length 163.6
  Top Layer L1 w19.68: v2(3571.54,1504.43) 3571.54,1523.92 R181.2@3572.61,1525
  Bottom Layer - L10 w9.84: U23.7@3565.72,1385.28 3565.72,1498.61 v2(3571.54,1504.43)
  Bottom Layer - L10 w19.68: v2(3571.54,1504.43) 3571.54,1523.92 C309.2@3572.61,1525
NetC311_1: C311.1 U30.5 | length 102.3
  Top Layer L1 w15.75: C311.1@677.32,1805 681.02,1808.7 v2(681.02,1861.52)
  Bottom Layer - L10 w15.75: U30.5@681.02,1817.32 v2(681.02,1861.52)
NetC312_1: C312.1 U31.5 | length 102.3
  Top Layer L1 w15.75: C312.1@677.32,2105 681.02,2108.7 v2(681.02,2161.52)
  Bottom Layer - L10 w15.75: U31.5@681.02,2117.32 v2(681.02,2161.52)
NetC313_1: C313.1 U32.5 | length 102.3
  Top Layer L1 w15.75: C313.1@1989.32,2405 1993.02,2408.7 v2(1993.02,2461.52)
  Bottom Layer - L10 w15.75: U32.5@1993.02,2417.32 v2(1993.02,2461.52)
NetC314_1: C314.1 U33.5 | length 102.3
  Top Layer L1 w15.75: C314.1@2366.32,2405 2370.02,2408.7 v2(2370.02,2461.52)
  Bottom Layer - L10 w15.75: U33.5@2370.02,2417.32 v2(2370.02,2461.52)
NetC315_1: C315.1 U34.5 | length 102.3
  Top Layer L1 w15.75: C315.1@1141.32,2105 1145.02,2108.7 v2(1145.02,2161.52)
  Bottom Layer - L10 w15.75: U34.5@1145.02,2117.32 v2(1145.02,2161.52)
NetC316_1: C316.1 U35.5 | length 102.3
  Top Layer L1 w15.75: C316.1@1518.32,2105 1522.02,2108.7 v2(1522.02,2161.52)
  Bottom Layer - L10 w15.75: U35.5@1522.02,2117.32 v2(1522.02,2161.52)
NetC317_1: C317.1 U36.5 | length 102.3
  Top Layer L1 w15.75: C317.1@1141.32,2405 1145.02,2408.7 v2(1145.02,2461.52)
  Bottom Layer - L10 w15.75: U36.5@1145.02,2417.32 v2(1145.02,2461.52)
NetC318_1: C318.1 U37.5 | length 102.3
  Top Layer L1 w15.75: C318.1@1518.32,2405 1522.02,2408.7 v2(1522.02,2461.52)
  Bottom Layer - L10 w15.75: U37.5@1522.02,2417.32 v2(1522.02,2461.52)
NetC319_1: C319.1 U38.5 | length 102.3
  Top Layer L1 w15.75: C319.1@1989.32,2105 1993.02,2108.7 v2(1993.02,2161.52)
  Bottom Layer - L10 w15.75: U38.5@1993.02,2117.32 v2(1993.02,2161.52)
NetC320_1: C320.1 U39.5 | length 102.3
  Top Layer L1 w15.75: C320.1@2367.32,2105 C320.1@2371.02,2108.7 ; C320.1@2370.02,2108.7 v2(2370.02,2161.52)
  Bottom Layer - L10 w15.75: U39.5@2370.02,2117.32 v2(2370.02,2161.52)
NetC321_1: C321.1 R213.2 U30.6 U30.7 | length 133.2
  Top Layer L1 w15.75: R213.2@643.12,1773.13 C321.1@677.32,1773.13
  Bottom Layer - L10 w15.75: U30.7@629.84,1817.32 629.84,1785.92 v2(642.63,1773.13) 655.43,1785.92 U30.6@655.43,1817.32
NetC322_1: C322.1 R214.2 U31.6 U31.7 | length 133.2
  Top Layer L1 w15.75: R214.2@643.13,2073.13 C322.1@677.32,2073.13
  Bottom Layer - L10 w15.75: U31.7@629.84,2117.32 629.84,2085.92 v2(642.63,2073.13) 655.43,2085.92 U31.6@655.43,2117.32
NetC323_1: C323.1 R215.2 U32.6 U32.7 | length 133.2
  Top Layer L1 w15.75: R215.2@1955.13,2373.13 C323.1@1989.32,2373.13
  Bottom Layer - L10 w15.75: U32.7@1941.84,2417.32 1941.84,2385.92 v2(1954.63,2373.13) 1967.43,2385.92 U32.6@1967.43,2417.32
NetC324_1: C324.1 R216.2 U33.6 U33.7 | length 133.2
  Top Layer L1 w15.75: R216.2@2332.13,2373.13 C324.1@2366.32,2373.13
  Bottom Layer - L10 w15.75: U33.7@2318.84,2417.32 2318.84,2385.92 v2(2331.63,2373.13) 2344.43,2385.92 U33.6@2344.43,2417.32
NetC325_1: C325.1 R217.2 U34.6 U34.7 | length 133.2
  Top Layer L1 w15.75: R217.2@1107.13,2073.13 C325.1@1141.32,2073.13
  Bottom Layer - L10 w15.75: U34.7@1093.84,2117.32 1093.84,2085.92 v2(1106.63,2073.13) 1119.43,2085.92 U34.6@1119.43,2117.32
NetC326_1: C326.1 R218.2 U35.6 U35.7 | length 133.2
  Top Layer L1 w15.75: R218.2@1484.13,2073.13 C326.1@1518.32,2073.13
  Bottom Layer - L10 w15.75: U35.7@1470.84,2117.32 1470.84,2085.92 v2(1483.63,2073.13) 1496.43,2085.92 U35.6@1496.43,2117.32
NetC327_1: C327.1 R219.2 U36.6 U36.7 | length 133.2
  Top Layer L1 w15.75: R219.2@1107.13,2373.13 C327.1@1141.32,2373.13
  Bottom Layer - L10 w15.75: U36.7@1093.84,2417.32 1093.84,2385.92 v2(1106.63,2373.13) 1119.43,2385.92 U36.6@1119.43,2417.32
NetC328_1: C328.1 R220.2 U37.6 U37.7 | length 133.2
  Top Layer L1 w15.75: R220.2@1484.13,2373.13 C328.1@1518.32,2373.13
  Bottom Layer - L10 w15.75: U37.7@1470.84,2417.32 1470.84,2385.92 v2(1483.63,2373.13) 1496.43,2385.92 U37.6@1496.43,2417.32
NetC329_1: C329.1 R221.2 U38.6 U38.7 | length 133.2
  Top Layer L1 w15.75: R221.2@1955.13,2073.13 C329.1@1989.32,2073.13
  Bottom Layer - L10 w15.75: U38.7@1941.84,2117.32 1941.84,2085.92 v2(1954.63,2073.13) 1967.43,2085.92 U38.6@1967.43,2117.32
NetC330_1: C330.1 R222.2 U39.6 U39.7 | length 133.2
  Top Layer L1 w15.75: R222.2@2333.13,2073.13 C330.1@2367.32,2073.13
  Bottom Layer - L10 w15.75: U39.7@2319.84,2117.32 2319.84,2085.92 v2(2332.63,2073.13) 2345.43,2085.92 U39.6@2345.43,2117.32
NetC341_1: C341.1 R224.1 U33.2 | length 211.3
  Top Layer L1 w15.75: v2(2318.84,2538.48) 2318.84,2553.09 R224.1@2324.74,2559
  Bottom Layer - L10 w8: C341.1@2219.33,2636 2303.92,2636 2318.84,2621.08 U33.2@2318.84,2582.68
  Bottom Layer - L10 w15.75: v2(2318.84,2538.48) U33.2@2318.84,2582.68
NetC342_1: C342.1 R225.1 U35.2 | length 211.3
  Top Layer L1 w15.75: v2(1470.84,2238.48) 1470.84,2253.09 R225.1@1476.74,2259
  Bottom Layer - L10 w8: C342.1@1371.33,2336 1455.92,2336 1470.84,2321.08 U35.2@1470.84,2282.68
  Bottom Layer - L10 w15.75: v2(1470.84,2238.48) U35.2@1470.84,2282.68
NetC343_1: C343.1 R226.1 U37.2 | length 211.3
  Top Layer L1 w15.75: v2(1470.84,2538.48) 1470.84,2553.09 R226.1@1476.74,2559
  Bottom Layer - L10 w8: C343.1@1371.33,2636 1455.92,2636 1470.84,2621.08 U37.2@1470.84,2582.68
  Bottom Layer - L10 w15.75: v2(1470.84,2538.48) U37.2@1470.84,2582.68
NetC344_1: C344.1 R227.1 U38.2 | length 167.9
  Top Layer L1 w15.75: v2(1941.84,2238.48) 1941.84,2253.09 R227.1@1947.74,2259
  Bottom Layer - L10 w8: C344.1@1885.68,2336 1926.92,2336 1941.84,2321.08 U38.2@1941.84,2282.68
  Bottom Layer - L10 w15.75: v2(1941.84,2238.48) U38.2@1941.84,2282.68
NetC344_2: C344.2 TP41_4.1 U41.4 | length 143.1
  Bottom Layer - L10 w8: U41.4@1724.58,2366.4 1724.58,2351.4 TP41_4.1@1794,2351.4 1809.4,2336 C344.2@1846.31,2336
NetC345_1: C345.1 R228.1 U39.2 | length 212.3
  Top Layer L1 w15.75: v2(2319.84,2238.48) 2319.84,2253.09 R228.1@2325.74,2259
  Bottom Layer - L10 w8: C345.1@2219.33,2336 2304.92,2336 2319.84,2321.08 U39.2@2319.84,2282.68
  Bottom Layer - L10 w15.75: v2(2319.84,2238.48) U39.2@2319.84,2282.68
NetC350_1: C350.1 OFFSET.1 R229.1 R233.2 | length 219.2
  Bottom Layer - L10 w15.75: R233.2@446.69,1648.4 C350.1@446.68,1611 OFFSET.1@501,1611 ; OFFSET.1@525,1611 R229.1@615.16,1520.84
NetC351_1: C351.1 R230.1 | length 35.6
  Bottom Layer - L10 w8: C351.1@265,1355.16 R230.1@265,1390.79
NetC352_1: C352.1 D3.3 K1.9 VIN.1 | length 664.2
  Bottom Layer - L10 w8: VIN.1@100,1275 188,1275 348,1115 D3.3@484.68,1115 C352.1@484.68,1175.16 560,1175.16 K1.9@615,1230.16
NetC352_2: C352.2 K1.6 | length 153.1
  Bottom Layer - L10 w8: K1.6@315,1230.16 370,1175.16 C352.2@445.31,1175.16
NetC370_2: C370.2 C371.2 K3.6 R191.2 R192.1 | length 487.2
  Bottom Layer - L10 w8: K3.6@1393,1230.16 1472,1151.16 C370.2@1743,1151.16 R191.2@1777,1151.16 R192.1@1813.32,1151.16 C371.2@1813.31,1185.31
NetC371_1: C371.1 C372.2 K4.9 R192.2 R193.2 | length 487.2
  Bottom Layer - L10 w8: C371.1@1852.68,1185.31 R192.2@1852.69,1151.16 R193.2@1889,1151.16 C372.2@1923,1151.16 2194,1151.16 K4.9@2273,1230.16
NetC373_2: C373.2 C374.2 K3.9 R194.2 R195.1 | length 162.3
  Bottom Layer - L10 w8: K3.9@1693,1230.16 1743,1230.16 C373.2@1743,1237.97 R194.2@1777,1237.97 R195.1@1813.32,1237.97 C374.2@1813.31,1272.12
NetC374_1: C374.1 C375.2 K4.6 R195.2 R196.2 | length 162.3
  Bottom Layer - L10 w8: C374.1@1852.68,1272.12 R195.2@1852.69,1237.97 R196.2@1889,1237.97 C375.2@1923,1237.97 1923,1230.16 K4.6@1973,1230.16
NetC376_1: C376.1 C377.2 K3.1 R197.1 R198.1 | length 162.3
  Bottom Layer - L10 w8: K3.1@1693,1430.16 1743,1430.16 C376.1@1743,1422.34 R197.1@1777,1422.34 R198.1@1813.32,1422.34 C377.2@1813.31,1388.19
NetC377_1: C377.1 C378.1 K4.4 R198.2 R199.1 | length 162.3
  Bottom Layer - L10 w8: C377.1@1852.68,1388.19 R198.2@1852.69,1422.34 R199.1@1889,1422.34 C378.1@1923,1422.34 1923,1430.16 K4.4@1973,1430.16
NetC379_2: C379.2 C380.2 K3.4 R200.2 R201.1 | length 487.2
  Bottom Layer - L10 w8: K3.4@1393,1430.16 1472,1509.16 C379.2@1743,1509.16 R200.2@1777,1509.16 R201.1@1813.32,1509.16 C380.2@1813.31,1475
NetC380_1: C380.1 C381.2 K4.1 R201.2 R202.2 | length 487.2
  Bottom Layer - L10 w8: C380.1@1852.68,1475 R201.2@1852.69,1509.16 R202.2@1889,1509.16 C381.2@1923,1509.16 2194,1509.16 K4.1@2273,1430.16
NetC384_1: C384.1 U43.6 | length 56.6
  Top Layer L1 w9.45: U43.6@1629.79,958.37 C384.1@1629.79,1015
NetC385_1: C385.1 C403.1 R244.2 R245.1 U43.8 | length 250.1
  Top Layer L1 w9.45: C385.1@1497.68,1065.02 C403.1@1497.68,1018 R245.1@1497.68,979 R244.2@1535,979 1595,919 U43.8@1636.88,919
NetC393_1: C393.1 L51.1 R246.2 U44.5 | length 164.9
  Top Layer L1 w24: R246.2@234.11,2163.44 243.95,2153.6 U44.5@287.87,2153.6
  Top Layer L1 w31.5: L51.1@127,2163.44 C393.1@185,2163.44 R246.2@234.11,2163.44
NetC406_1: C406.1 C407.1 L53.2 U45.1 | length 146.1
  Top Layer L1 w24: U45.1@751.13,915.6 796.03,915.6 C407.1@804.89,906.74 v3(804.89,878.49) L53.2@804.89,846.31
  Bottom Layer - L10 w24: v3(804.89,878.49) C406.1@804.89,906.74
NetC408_1: C408.1 U45.4 | length 59.6
  Top Layer L1 w24: U45.4@642.87,990.4 C408.1@642.87,1050
NetC409_1: C409.1 L54.1 R248.1 U45.6 | length 167.7
  Top Layer L1 w24: R248.1@589.11,906.74 597.97,915.6 U45.6@642.87,915.6
  Top Layer L1 w31.5: L54.1@530.03,850.01 530.03,895.66 C409.1@541.11,906.74 R248.1@590.11,906.74
NetC409_2: C409.2 R248.2 R249.2 U45.5 | length 153
  Top Layer L1 w24: C409.2@541.11,961.86 R248.2@590.11,961.86 ; R249.2@589.11,1008.44 R248.2@589.11,961.86 597.97,953 U45.5@642.87,953
NetC415_1: C415.1 C416.1 L40.2 U48.D2
NetC417_2: C417.2 R257.1 R258.2 U48.A2 | length 125.3
  Top Layer L1 w8: U48.A2@2194.86,898.65 2194.86,940.02 R258.2@2202.67,940.02
  Top Layer L1 w19: R258.2@2202.67,940.02 2214.36,951.71 R257.1@2238.99,951.71 C417.2@2273.99,951.71
NetD1_1: D1.1 L37.1 U21.D1
NetD7_1: D7.1 L41.1 U48.D1
"NetDC COUPLED_1": "DC COUPLED.1" R255.1 | length 63.2
  Top Layer L1 w24: R255.1@4039,182.3 4039,245.47
NetDC_2: DC.2 R234.1 U30.2 | length 256.4
  Top Layer L1 w15.75: DC.2@492.52,1900 591.36,1900 v2(629.84,1938.48) 629.84,1989.09 R234.1@635.74,1995
  Bottom Layer - L10 w15.75: v2(629.84,1938.48) U30.2@629.84,1982.68
NetEXT_Vcmo_2: EXT_Vcmo.2 R182.2 R183.2 Vcmo.1 | length 238.6
  Bottom Layer - L10 w19.68: R183.2@3801.78,757.69 3801.78,777 R182.2@3801.78,796.31
  Bottom Layer - L10 w25: EXT_Vcmo.2@3701.78,777 Vcmo.1@3901.78,777
NetFMC_RX1_C39: FMC_RX1.C39 FMC_RX1.D36 FMC_RX1.D38 FMC_RX1.D40 R132.2 | length 727.6
  Top Layer L1 w18: R132.2@8147.56,515 v1(8172.31,515) ; v1(8563,490) v1(8563,540)
  Signals - L3 w18: v1(8172.31,515) 8563,515 ; v1(8563,490) v1(8563,540)
  Bottom Layer - L10 w18: v1(8563,490) FMC_RX1.D38@8588,465 FMC_RX1.C39@8638,415 FMC_RX1.D40@8588,365 ; v1(8563,540) FMC_RX1.D36@8588,565
NetFMC_RX1_D30: "KC705 JTAG.1" FMC_RX1.D30 | length 789.5
  Signals - L3 w4: 8054,915 8625,915 8638,902 8638,828 8625,815 8588,815 v5(8563,840)
  Bottom Layer - L10 w8: v5(8563,840) FMC_RX1.D30@8588,865
NetFMC_RX1_D31: "KC705 JTAG.2" FMC_RX1.D31 | length 1110.2
  Signals - L3 w4: 7954,915 8004,965 8675,965 8688,952 8688,778 8675,765 8588,765 v5(8563,790)
  Bottom Layer - L10 w8: v5(8563,790) FMC_RX1.D31@8588,815
NetJ2_1: J2.1 L31.2 | length 80.3
  Top Layer L1 w19.68: J2.1@5876,1415 L31.2@5956.31,1415
NetJ3_1: J3.1 uWIRE.10 | length 205
  Top Layer L1 w25: J3.1@6495,640 uWIRE.10@6700,640
NetK1_1: K1.1 R229.2 | length 51.2
  Bottom Layer - L10 w8: K1.1@615,1430.16 R229.2@615,1481.31
NetK1_2: K1.2 K2.7 | length 654.5
  Bottom Layer - L10 w8: K1.2@515,1430.16 566,1379.16 699,1379.16 801,1481.16 1034,1481.16 K2.7@1085,1430.16
NetK1_4: K1.4 R230.2 | length 50
  Bottom Layer - L10 w8: R230.2@265,1430.16 K1.4@315,1430.16
NetK1_7: K1.7 K2.2 | length 654.5
  Bottom Layer - L10 w8: K1.7@415,1230.16 466,1281.16 699,1281.16 801,1179.16 934,1179.16 K2.2@985,1230.16
NetK2_1: K2.1 K3.7 | length 650.2
  Bottom Layer - L10 w8: K2.1@885,1230.16 936,1281.16 1442,1281.16 K3.7@1493,1230.16
NetK2_4: K2.4 K5.1 | length 1456.5
  Bottom Layer - L10 w8: K2.4@1185,1230.16 1303.84,1111.31 2424.16,1111.31 K5.1@2543,1230.16
NetK2_6: K2.6 K5.9 | length 1456.5
  Bottom Layer - L10 w8: K2.6@1185,1430.16 1303.84,1549 2424.16,1549 K5.9@2543,1430.16
NetK2_9: K2.9 K3.2 | length 750.2
  Bottom Layer - L10 w8: K2.9@885,1430.16 936,1379.16 1542,1379.16 K3.2@1593,1430.16
NetK4_2: K4.2 K5.6 | length 712.2
  Bottom Layer - L10 w8: K4.2@2173,1430.16 2224,1379.16 2792,1379.16 K5.6@2843,1430.16
NetK4_7: K4.7 K5.4 | length 812.2
  Bottom Layer - L10 w8: K4.7@2073,1230.16 2124,1281.16 2792,1281.16 K5.4@2843,1230.16
NetK6_7: K6.7 K7.12 | length 125
  Top Layer L1 w24: K6.7@2989,76 K7.12@3114,76
NetK6_10: K6.10 R252.2 | length 100
  Top Layer L1 w24: K6.10@2689,76 R252.2@2789,76
NetK6_12: K6.12 R251.1 | length 100
  Top Layer L1 w24: K6.12@2489,76 R251.1@2589,76
NetK7_10: K7.10 R253.1 | length 100
  Top Layer L1 w24: K7.10@3314,76 R253.1@3414,76
NetK8_10: K8.10 R255.2 | length 100
  Top Layer L1 w24: K8.10@3939,76 R255.2@4039,76
NetK8_12: K8.12 R254.1 | length 100
  Top Layer L1 w24: K8.12@3739,76 R254.1@3839,76
NetL6_1: L6.1 LMX_LDO.2 R73.2 | length 197.9
  Top Layer L1 w37: L6.1@6914,1939.5 LMX_LDO.2@6914,2040
  Bottom Layer - L10 w51: R73.2@6906.91,2134.44 6906.91,2047.09 LMX_LDO.2@6914,2040
NetL9_1: L9.1 L10.1 L13.1 LMK_LDO.2 R40.2 | length 496.5
  Top Layer L1 w37: L13.1@5954,2040 LMK_LDO.2@6126,2040 ; L10.1@6026,2103 6063,2103 LMK_LDO.2@6126,2040 ; L9.1@6126,1940 LMK_LDO.2@6126,2040
  Bottom Layer - L10 w51: R40.2@6118.91,2135.44 6118.91,2047.09 LMK_LDO.2@6126,2040
NetL44_1: L44.1 L46.1 R176.2 U22.5 | length 211.4
  Top Layer L1 w24: U22.5@2535.6,733.24 2535.6,777.16 R176.2@2545.44,787
  Top Layer L1 w31.5: L46.1@2475.01,808.97 2507.71,808.97 2529.68,787 R176.2@2545.44,787
  Top Layer L1 w37.4: L46.1@2475.01,808.97 L44.1@2475.01,883.03
NetL48_1: L48.1 L52.1 R231.2 U42.5 | length 203.7
  Top Layer L1 w24: R231.2@185.56,1778.11 195.4,1787.95 U42.5@195.4,1831.87
  Top Layer L1 w31.5: R231.2@185.56,1778.11 193.75,1769.92 L48.1@255.99,1769.92
  Top Layer L1 w37.4: L48.1@255.99,1769.92 L52.1@328,1769.92
NetL49_1: L49.1 U43.1
NetL49_2: L49.2 U43.10
NetL55_2: L55.2 R179.1 R184.1 | length 73.1
  Top Layer L1 w16: R184.1@3894.79,1307.55 v1(3915.6,1307.55)
  Bottom Layer - L10 w8: L55.2@3919.2,1296.47 3919.2,1312.55 3952.71,1312.55 R179.1@3954.63,1314.47
NetL56_2: L56.2 R180.1 R185.2 | length 73.1
  Top Layer L1 w16: R185.2@3894.79,1352.76 v1(3915.6,1352.76)
  Bottom Layer - L10 w8: L56.2@3919.2,1363.84 3919.2,1347.76 3952.71,1347.76 R180.1@3954.63,1345.84
NetLD1_1: LD1.1 Status1.1 U6.31 | length 330.1
  Top Layer L1 w9: U6.31@4390.79,2274.95 Status1.1@4587.98,2274.95 LD1.1@4681.93,2181
NetLD2_1: LD2.1 Status2.1 U6.48 | length 473.5
  Top Layer L1 w9: LD2.1@3818,2561 Status2.1@3888.71,2561 ; Status2.1@3889,2561 3889,2373 3916,2346 4064.65,2346 4069.92,2340.73 U6.48@4069.92,2320.23
NetLF1_1: LF1.1 LF2.1 U6.46 | length 136.1
  Top Layer L1 w5.5: LF2.1@4076.86,2386.74 4090.86,2372.74 4101.3,2372.74 4109.29,2364.75 U6.46@4109.29,2320.23
  Top Layer L1 w15: LF2.1@4076.86,2386.74 LF1.1@4076.86,2436.74
NetLF1_2: LF1.2 LF3.2 | length 51.9
  Top Layer L1 w15: LF3.2@3969.86,2436.74 LF1.2@4021.74,2436.74
NetLF7_2: LF7.2 S1.1 | length 171
  Bottom Layer - L10 w50: S1.1@1295.1,100.2 1407.5,212.6 LF7.2@1419.55,212.6
NetLMKCLK_1: LMKCLK.1 R48.2 R51.2 | length 216.1
  Top Layer L1 w8: R48.2@4395.36,2482.51 R51.2@4432.67,2482.5 LMKCLK.1@4611.5,2482.51
"NetOFFSET ADJ_2": "OFFSET ADJ.2" U40.4 | length 103.7
  Bottom Layer - L10 w15.75: v2(169.09,1623) 218.49,1573.6 U40.4@252.33,1573.6
NetOR_T0_1: OR_T0.1 U1.1 | length 71.5
  Top Layer L1 w19.5: U1.1@6006,1232.52 OR_T0.1@6077.47,1232.52
NetOR_T0_2: OR_T0.2 R2.1
  other v1: 6136.53,1232.52
NetOR_T1_1: OR_T1.1 U1.7 | length 169.1
  Top Layer L1 w19.5: U1.7@5956,1047.48 5956,1079 5981,1104 6063.47,1104 OR_T1.1@6077.47,1090
NetOR_T1_2: OR_T1.2 R10.1
  other v1: 6136.53,1090
NetOSCin_1: OSCin.1 R25.1 R30.2 | length 242.7
  Top Layer L1 w8: R30.2@5583.65,1950.78 R25.1@5623.02,1950.78 5693.24,2021 OSCin.1@5693.24,2125
NetQ1_4: Q1.4 U47.4 | length 58.8
  Top Layer L1 w25: Q1.4@2049.3,223.62 v3(2049.3,250.1)
  Bottom Layer - L10 w23.62: v3@2049.3,250 U47.4@2049.3,282.28
NetQ2_2: Q2.2 U26.4 | length 516.9
  Top Layer L1 w8: v2(1642,1973.85) 1667.35,1948.5 1974.27,1948.5 2010,1912.77 2010,1866.77 2020.39,1856.39 Q2.2@2045,1856.39
  Bottom Layer - L10 w8: v2(1642,1973.85) U26.4@1642,2012.14
NetQ2_3: Q2.3 R260.1 | length 2829.9
  Top Layer L1 w8: Q2.3@2045,1836.39 2045,1819.65 2081,1783.65 v2(2095,1783.65) ; R260.1@3862.56,376 v2(3890.04,376)
  Signals - L8 w8: v2(2095,1783.65) 2170.65,1708 2300.71,1708 2373,1635.71 2373,1519 2423,1469 2423,1215 ; 2422.5,1215.5 2710,928 2710,890 2798,802 2798,627 2873,552 3714.04,552 v2(3890.04,376)
NetQ2_5: Q2.5 U26.6 | length 580.1
  Top Layer L1 w8: v2(1693.18,1972.5) 2059.27,1972.5 2130,1901.77 2130,1866.77 2119.61,1856.39 Q2.5@2095,1856.39
  Bottom Layer - L10 w8: v2(1693.18,1972.5) U26.6@1693.18,2012.14
NetQ2_6: Q2.6 R259.1 | length 3341.9
  Top Layer L1 w8: Q2.6@2095,1876.39 v2(2095,1894.12) ; R259.1@4362.56,376 v2(4391.04,376)
  Signals - L8 w8: v2(2095,1894.12) 2279.88,1894.12 2543,1631 2543,1519 2593,1469 2593,1205 2833,965 3038,965 3062,941 3062,684 3154,592 4175.04,592 v2(4391.04,376)
NetQ3_2: Q3.2 U26.8 | length 114.8
  Top Layer L1 w8: v2(1718.77,1856.39) Q3.2@1757,1856.39
  Bottom Layer - L10 w8: U26.8@1718.77,1779.86 v2(1718.77,1856.39)
NetQ3_3: Q3.3 R262.1 | length 2920.7
  Top Layer L1 w8: v2(1757,1818.65) Q3.3@1757,1836.39 ; v2(3462.96,376) R262.1@3490.44,376
  Signals - L8 w8: v2(1757,1818.65) 1782,1843.65 1782,1913 1817.5,1948.5 1974.27,1948.5 2010,1912.77 2010,1818.12 2163.12,1665 2243.71,1665 2273,1635.71 2273,1519 2323,1469 2323,1191 2430,1084 2481,1084 2624,941 2624,707 2819,512 3326.96,512 v2(3462.96,376)
NetQ3_5: Q3.5 U26.12 | length 360
  Top Layer L1 w8: v2(1616.41,1818.15) 1646.29,1788.27 1819.27,1788.27 1842,1811 1842,1846 1831.61,1856.39 Q3.5@1807,1856.39
  Bottom Layer - L10 w8: U26.12@1616.41,1779.86 v2(1616.41,1818.15)
NetQ3_6: Q3.6 R261.1 | length 2623
  Top Layer L1 w8: Q3.6@1807,1876.39 v2(1807,1894.12) ; R261.1@3169.12,307.56 v2(3196.6,307.56)
  Signals - L8 w8: v2(1807,1894.12) 1837.38,1924.5 1963.27,1924.5 1986,1901.77 1986,1790.94 2123,1653.94 2123,1569 2223,1469 2223,1191 2369,1045 2463,1045 2574,934 2574,643 2745,472 3131,472 3196.6,406.4 v2(3196.6,307.56)
NetQ4_2: Q4.2 U26.10 | length 346.2
  Top Layer L1 w8: v2(1667.59,1741.57) 1690.3,1764.27 1830.27,1764.27 1866,1800 1866,1846 1876.39,1856.39 Q4.2@1901,1856.39
  Bottom Layer - L10 w8: v2(1667.59,1741.57) U26.10@1667.59,1779.86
